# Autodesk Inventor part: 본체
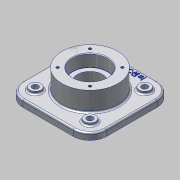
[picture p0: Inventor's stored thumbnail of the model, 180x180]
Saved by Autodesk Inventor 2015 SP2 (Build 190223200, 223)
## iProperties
Created: 2015-07
Part Number: 본체
Material: 알루미늄 6061
Document SubType Name: Modeling
Designer: AMC
Mass: 1462.04 g
Surface Area: 792.775 cm^2
Volume: 541.496 cm^3
Density: 2.7 g/cm^3
Appearance: 알루미늄 - 평지
Author: AMC
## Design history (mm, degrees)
sketch "스케치1"
  geometry: L1 (-75, -75)-(75, -75); L2 (75, -75)-(75, 75); L3 (75, 75)-(-75, 75); L4 (-75, 75)-(-75, -75); L5 (-75, -75)-(75, 75); L6 (75, -75)-(-75, 75); 1 further point
  constraints: 12 end point, 2 midpoint, 2 parallel, 1 horizontal, 1 perpendicular
  dimensions: "d0" = 150 distance of L3.end L2.end; "d1" = 150 distance of L2.end L1.end
extrude "돌출1" new body sketch "스케치1" distance "d2" = 12; taper "d3" = 0 deg
sketch "스케치2"
  geometry: C1 r 50 at (0, 0); 1 further point
  constraints: 1 centre point, 1 coincident
  dimensions: "d4" = 100 diameter of C1
extrude "돌출2" join sketch "스케치2" distance "d5" = 47; taper "d7" = 0 deg; dims "d6" = 23, "d8" = 0
fillet "모깎기1" dims "d9" = 30
sketch "스케치3"
  geometry: C1 r 10 at (-49, 49); C2 r 10 at (49, 49); C3 r 10 at (49, -49); C4 r 10 at (-49, -49); 1 further point
  constraints: 4 centre point, 2 horizontal alignment, 2 vertical alignment
  dimensions: "d10" = 20 diameter of C1; "d11" = 20 diameter of C2; "d12" = 20 diameter of C3; "d13" = 20 diameter of C4; "d14" = 49 horizontal distance of point (0, 0) C1.centre; "d15" = 98 distance of C2.centre C1.centre; "d16" = 49 horizontal distance of point (0, 0) C1.centre; "d17" = 98 distance of C4.centre C1.centre
extrude "돌출3" join sketch "스케치3" distance "d18" = 5; taper "d19" = 0 deg
hole "구멍1" diameter "d22" = 11; stored, may be unused: countersink angle "d26" = 90 deg, drill point angle "d28" = 118 deg; dims "d20" = 10, "d21" = 10, "d23" = 6.35, "d24" = 4, "d25" = 2, "d27" = 9.525
hole "구멍2" diameter "d31" = 11; stored, may be unused: countersink angle "d35" = 90 deg, drill point angle "d37" = 118 deg; dims "d29" = 10, "d30" = 10, "d32" = 6.35, "d33" = 4, "d34" = 2, "d36" = 9.525
hole "구멍3" diameter "d40" = 11; stored, may be unused: countersink angle "d44" = 90 deg, drill point angle "d46" = 118 deg; dims "d38" = 10, "d39" = 10, "d41" = 6.35, "d42" = 4, "d43" = 2, "d45" = 9.525
hole "구멍4" diameter "d49" = 11; stored, may be unused: countersink angle "d53" = 90 deg, drill point angle "d55" = 118 deg; dims "d47" = 10, "d48" = 10, "d50" = 6.35, "d51" = 4, "d52" = 2, "d54" = 9.525
hole "구멍5" diameter "d58" = 45; stored, may be unused: countersink angle "d62" = 90 deg, drill point angle "d64" = 118 deg; dims "d56" = 10, "d57" = 10, "d59" = 6.35, "d60" = 62, "d61" = 22, "d63" = 9.525
hole "구멍6" diameter "d67" = 45; stored, may be unused: countersink angle "d71" = 90 deg, drill point angle "d73" = 118 deg; dims "d65" = 10, "d66" = 10, "d68" = 6.35, "d69" = 62, "d70" = 22, "d72" = 9.525
fillet "모깎기2" dims "d74" = 0.3
sketch "스케치4" dims "d75" = 82
  geometry: L1 (0, 0)-(28.991, 28.991); L2 (0, 0)-(41, 0); 2 further points
  constraints: 4 end point, 2 coincident, 1 equal length, 1 horizontal, 3 other
  dimensions: "d76" = 45 deg angle of L2 L1
hole "구멍7" sketch "스케치4" at (28.991, 28.991) diameter "d77" = 4.917; stored, may be unused: countersink angle "d81" = 90 deg, drill point angle "d83" = 118 deg; dims "d78" = 10, "d79" = 62, "d80" = 22, "d82" = 13
sketch "스케치5"
  geometry: 2 further points
  constraints: 1 vertical alignment, 1 other
  dimensions: "d87" = 65 distance of point (0, 0) point (0, 65)
feature "엠보싱1" sketch "스케치5" dims "d0" = 150, "d1" = 150, "d16" = 49, "d88" = 1, "d89" = 0
fillet "모깎기3" dims "d90" = 3
chamfer "모따기1" distance "d91" = 1; stored, may be unused: second distance "d92" = 2, angle "d93" = 45 deg
sketch "스케치6" dims "d94" = 82
  geometry: L1 (0, 0)-(28.991, 28.991); L2 (0, 0)-(41, 0); 2 further points
  constraints: 4 end point, 2 coincident, 1 equal length, 1 horizontal, 3 other
  dimensions: "d95" = 45 deg angle of L2 L1
hole "구멍8" sketch "스케치6" at (28.991, 28.991) diameter "d96" = 4.917; stored, may be unused: countersink angle "d100" = 90 deg, drill point angle "d102" = 118 deg; dims "d97" = 10, "d98" = 62, "d99" = 22, "d101" = 13
node "솔리드1"
pattern_circular "원형 패턴1" dims angle "d85" = 360 deg
pattern_circular "원형 패턴2" dims angle "d104" = 360 deg
